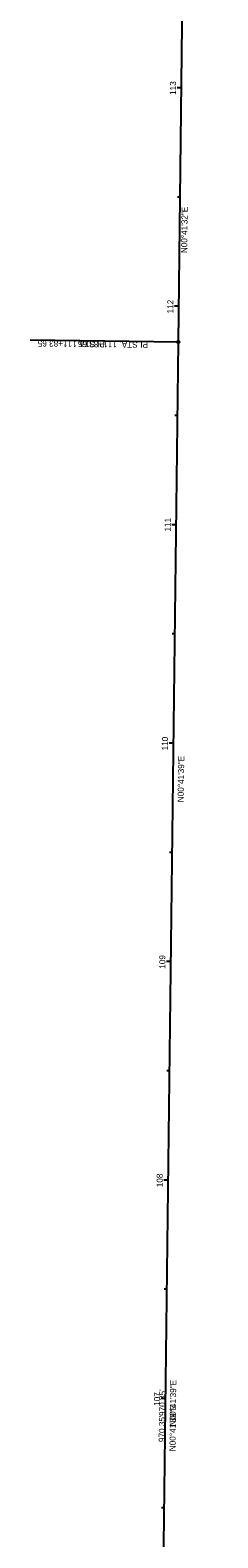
# Model space of a CAD drawing. Extents: x 1652464 to 1652574, y 605963 to 608691.
# Drawn here: x 1652484 to 1652570, y 606652 to 607342 of the extents above; entities that cross this region are included whole.
import ezdxf

# ---------------------------------------------------------------- set-up
doc = ezdxf.new("R2010")
doc.units = 0
for name, color, linetype in [('BR_X_SV_Abut', 7, 'Continuous'), ('DR_X_Erosion_Control', 7, 'Continuous'), ('DV_X_Property_Line', 7, 'Continuous'), ('DV_X_Section_VMS_Line', 7, 'Continuous'), ('DV_X_Text', 7, 'Continuous'), ('PV_X_Curb', 7, 'Continuous'), ('RW_X_CL', 7, 'Continuous'), ('RW_X_Fee_RW', 7, 'Continuous'), ('RW_X_Occupied_Area', 7, 'Continuous'), ('VG_X_Flower_Bed', 7, 'Continuous'), ('VG_X_Shrub_Line_Lt', 7, 'Continuous')]:
    doc.layers.add(name, color=color, linetype=linetype)

msp = doc.modelspace()

# ---------------------------------------------------------------- linework, layer by layer
at = {"layer": 'DV_X_Section_VMS_Line'}
for p, q in [((1652553.17, 607315.68), (1652551.17, 607315.7)), ((1652552.56, 607265.68), (1652551.36, 607265.7)), ((1652551.96, 607215.68), (1652549.96, 607215.71)), ((1652551.35, 607165.69), (1652550.15, 607165.7)), ((1652550.75, 607115.69), (1652548.75, 607115.72)), ((1652550.14, 607065.7), (1652548.94, 607065.71)), ((1652549.54, 607015.7), (1652547.54, 607015.72)), ((1652548.93, 606965.7), (1652547.73, 606965.72)), ((1652548.32, 606915.71), (1652546.32, 606915.73)), ((1652547.72, 606865.71), (1652546.52, 606865.72)), ((1652547.11, 606815.71), (1652545.11, 606815.74)), ((1652546.51, 606765.72), (1652545.31, 606765.73)), ((1652545.9, 606715.72), (1652543.9, 606715.75)), ((1652545.3, 606665.72), (1652544.1, 606665.74))]:
    msp.add_line(p, q, dxfattribs=at)
at = {"layer": 'DV_X_Text'}
for q in [(1652484.03, 607200.16), (1652506.76, 607199.88)]:
    msp.add_line((1652551.76, 607199.34), q, dxfattribs=at)
msp.add_circle((1652551.76, 607199.34), 0.6, dxfattribs=at)
msp.add_circle((1652551.76, 607199.34), 0.6, dxfattribs=at)
at = {"layer": 'PV_X_Curb'}
for p, q in [((1652551.76, 607199.34), (1652569.78, 608690.58)), ((1652540.01, 606229.06), (1652551.76, 607199.34))]:
    msp.add_line(p, q, dxfattribs=at)
at = {"layer": 'RW_X_CL'}
msp.add_circle((1652545.88, 606714.2), 0.05, dxfattribs=at)
msp.add_circle((1652545.88, 606714.2), 0.05, dxfattribs=at)
at = {"layer": 'RW_X_Occupied_Area'}
for p, q in [((1652551.76, 607199.34), (1652569.78, 608690.58)), ((1652551.76, 607199.34), (1652569.78, 608690.58)), ((1652540.01, 606229.06), (1652551.76, 607199.34)), ((1652540.01, 606229.06), (1652551.76, 607199.34))]:
    msp.add_line(p, q, dxfattribs=at)
at = {"layer": 'VG_X_Flower_Bed'}
msp.add_line((1652551.76, 607199.34), (1652506.76, 607199.88), dxfattribs=at)
msp.add_circle((1652551.76, 607199.34), 0.6, dxfattribs=at)
at = {"layer": 'VG_X_Shrub_Line_Lt'}
for p, q in [((1652553.17, 607315.68), (1652551.97, 607315.69)), ((1652551.96, 607215.68), (1652550.76, 607215.7)), ((1652550.75, 607115.69), (1652549.55, 607115.71)), ((1652549.54, 607015.7), (1652547.54, 607015.72)), ((1652548.32, 606915.71), (1652547.12, 606915.72)), ((1652547.11, 606815.71), (1652545.91, 606815.73)), ((1652545.9, 606715.72), (1652544.7, 606715.74))]:
    msp.add_line(p, q, dxfattribs=at)

# ---------------------------------------------------------------- texts
at = {"layer": 'BR_X_SV_Abut'}
msp.add_text('N00°41\'39"E', height=2.8, rotation=89.30592, dxfattribs=at).set_placement((1652550.55, 606702.96))
at = {"layer": 'DR_X_Erosion_Control'}
msp.add_text("970.35'", height=2.8, rotation=89.30592, dxfattribs=at).set_placement((1652545.76, 606707.71))
at = {"layer": 'DV_X_Property_Line'}
for s, rotation, p in [('N00°41\'32"E', 89.30765, (1652555.76, 607240.01)), ('N00°41\'39"E', 89.30592, (1652554.19, 606988.66)), ('N00°41\'39"E', 89.30592, (1652550.48, 606691.57))]:
    msp.add_text(s, height=2.8, rotation=rotation, dxfattribs=at).set_placement(p)
at = {"layer": 'DV_X_Section_VMS_Line'}
for s, rotation, p in [('113', 89.30765, (1652550.63, 607312.44)), ('112', 89.30765, (1652549.42, 607212.43)), ('111', 89.30592, (1652548.21, 607112.57)), ('110', 89.30592, (1652547, 607012.38)), ('109', 89.30592, (1652545.78, 606912.42)), ('108', 89.30592, (1652544.57, 606812.41)), ('107', 89.30592, (1652543.36, 606712.33))]:
    msp.add_text(s, height=2.8, rotation=rotation, dxfattribs=at).set_placement(p)
at = {"layer": 'DV_X_Text'}
for s, p in [('111+83.65', (1652505.32, 607199.87)), (' STA. ', (1652514.77, 607199.76)), ('PI', (1652518.17, 607199.72))]:
    msp.add_text(s, height=2.8, rotation=179.30765, dxfattribs=at).set_placement(p)
at = {"layer": 'RW_X_Fee_RW'}
msp.add_text("970.35'", height=2.8, rotation=89.30592, dxfattribs=at).set_placement((1652545.56, 606695.76))
at = {"layer": 'VG_X_Flower_Bed'}
for s, p in [('111+83.65', (1652523.66, 607199.63)), (' STA. ', (1652534.24, 607199.5)), ('PI', (1652537.94, 607199.46))]:
    msp.add_text(s, height=2.8, rotation=179.30765, dxfattribs=at).set_placement(p)
at = {"layer": 'VG_X_Shrub_Line_Lt'}
msp.add_text('110', height=2.8, rotation=89.30592, dxfattribs=at).set_placement((1652546.95, 607012.38))

doc.saveas('drawing.dxf')
